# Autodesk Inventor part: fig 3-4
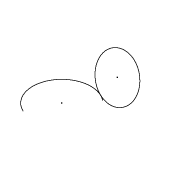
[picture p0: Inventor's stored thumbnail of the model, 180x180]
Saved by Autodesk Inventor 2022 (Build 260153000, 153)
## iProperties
Created: 2009-11
Part Number: fig 3-4
Document SubType Name: Modeling
Designer: Sham
Density: 1 g/cm^3
Material: Generic
Appearance: Default
Author: Sham
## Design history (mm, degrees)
sketch "Sketch1"
  geometry: A1 r 10.623 centre (-1.113, -21.203) between (5.463, -12.861) and (-5.537, -30.861); 1 further point; 1 other entity
  constraints: 2 point on circle, 1 centre point, 4 other
